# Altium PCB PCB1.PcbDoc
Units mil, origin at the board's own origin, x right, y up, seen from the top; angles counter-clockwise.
Board outline 2755.91 x 2519.69 mil, 4 copper layers (Top Layer, Layer 1, Layer 2, Bottom Layer), stack 23.756 mil thick; 44 components, 30 nets, 121 pads, 26 vias.
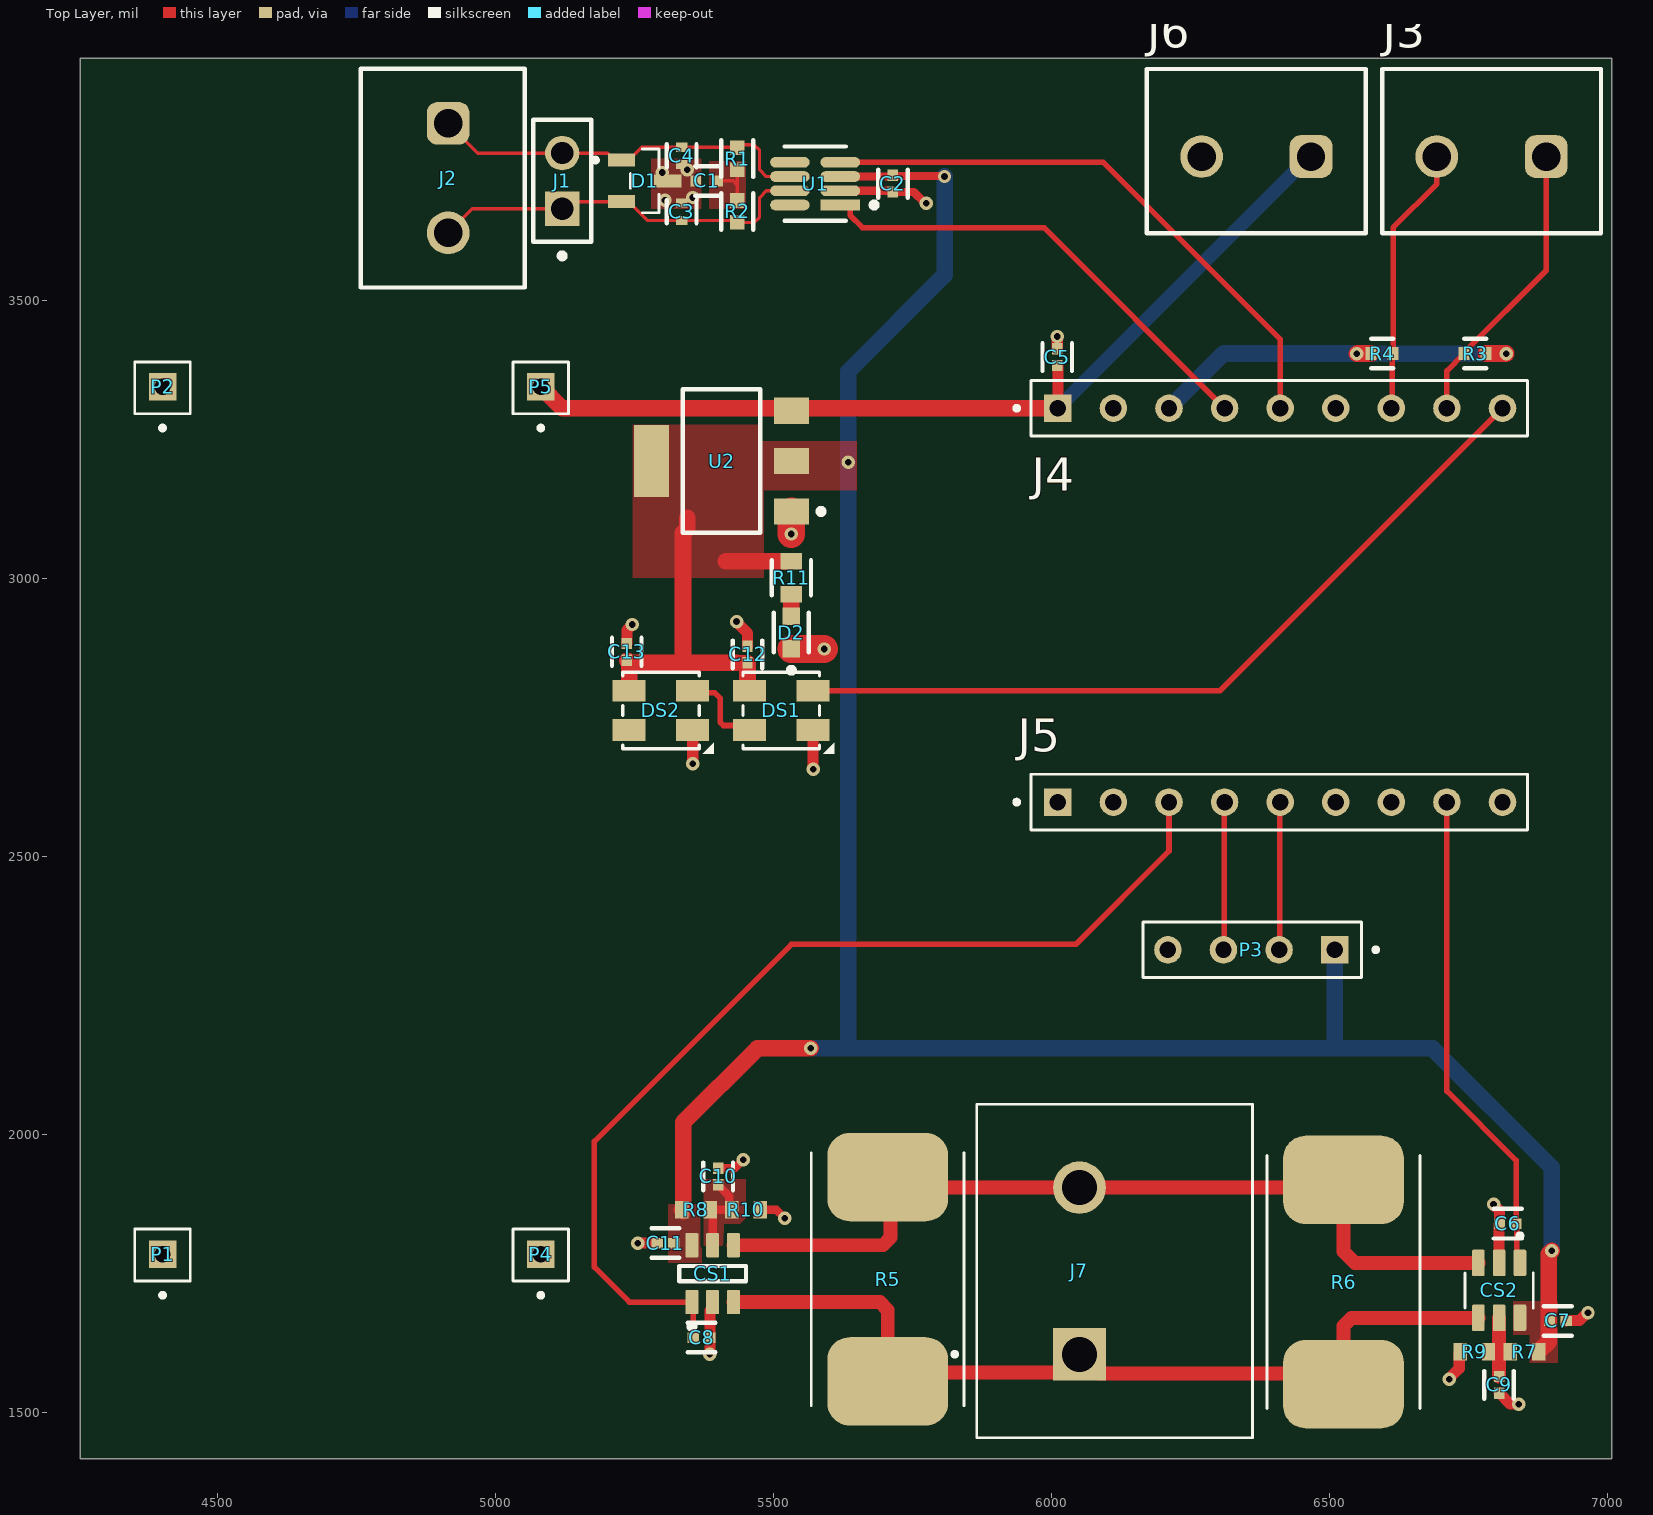
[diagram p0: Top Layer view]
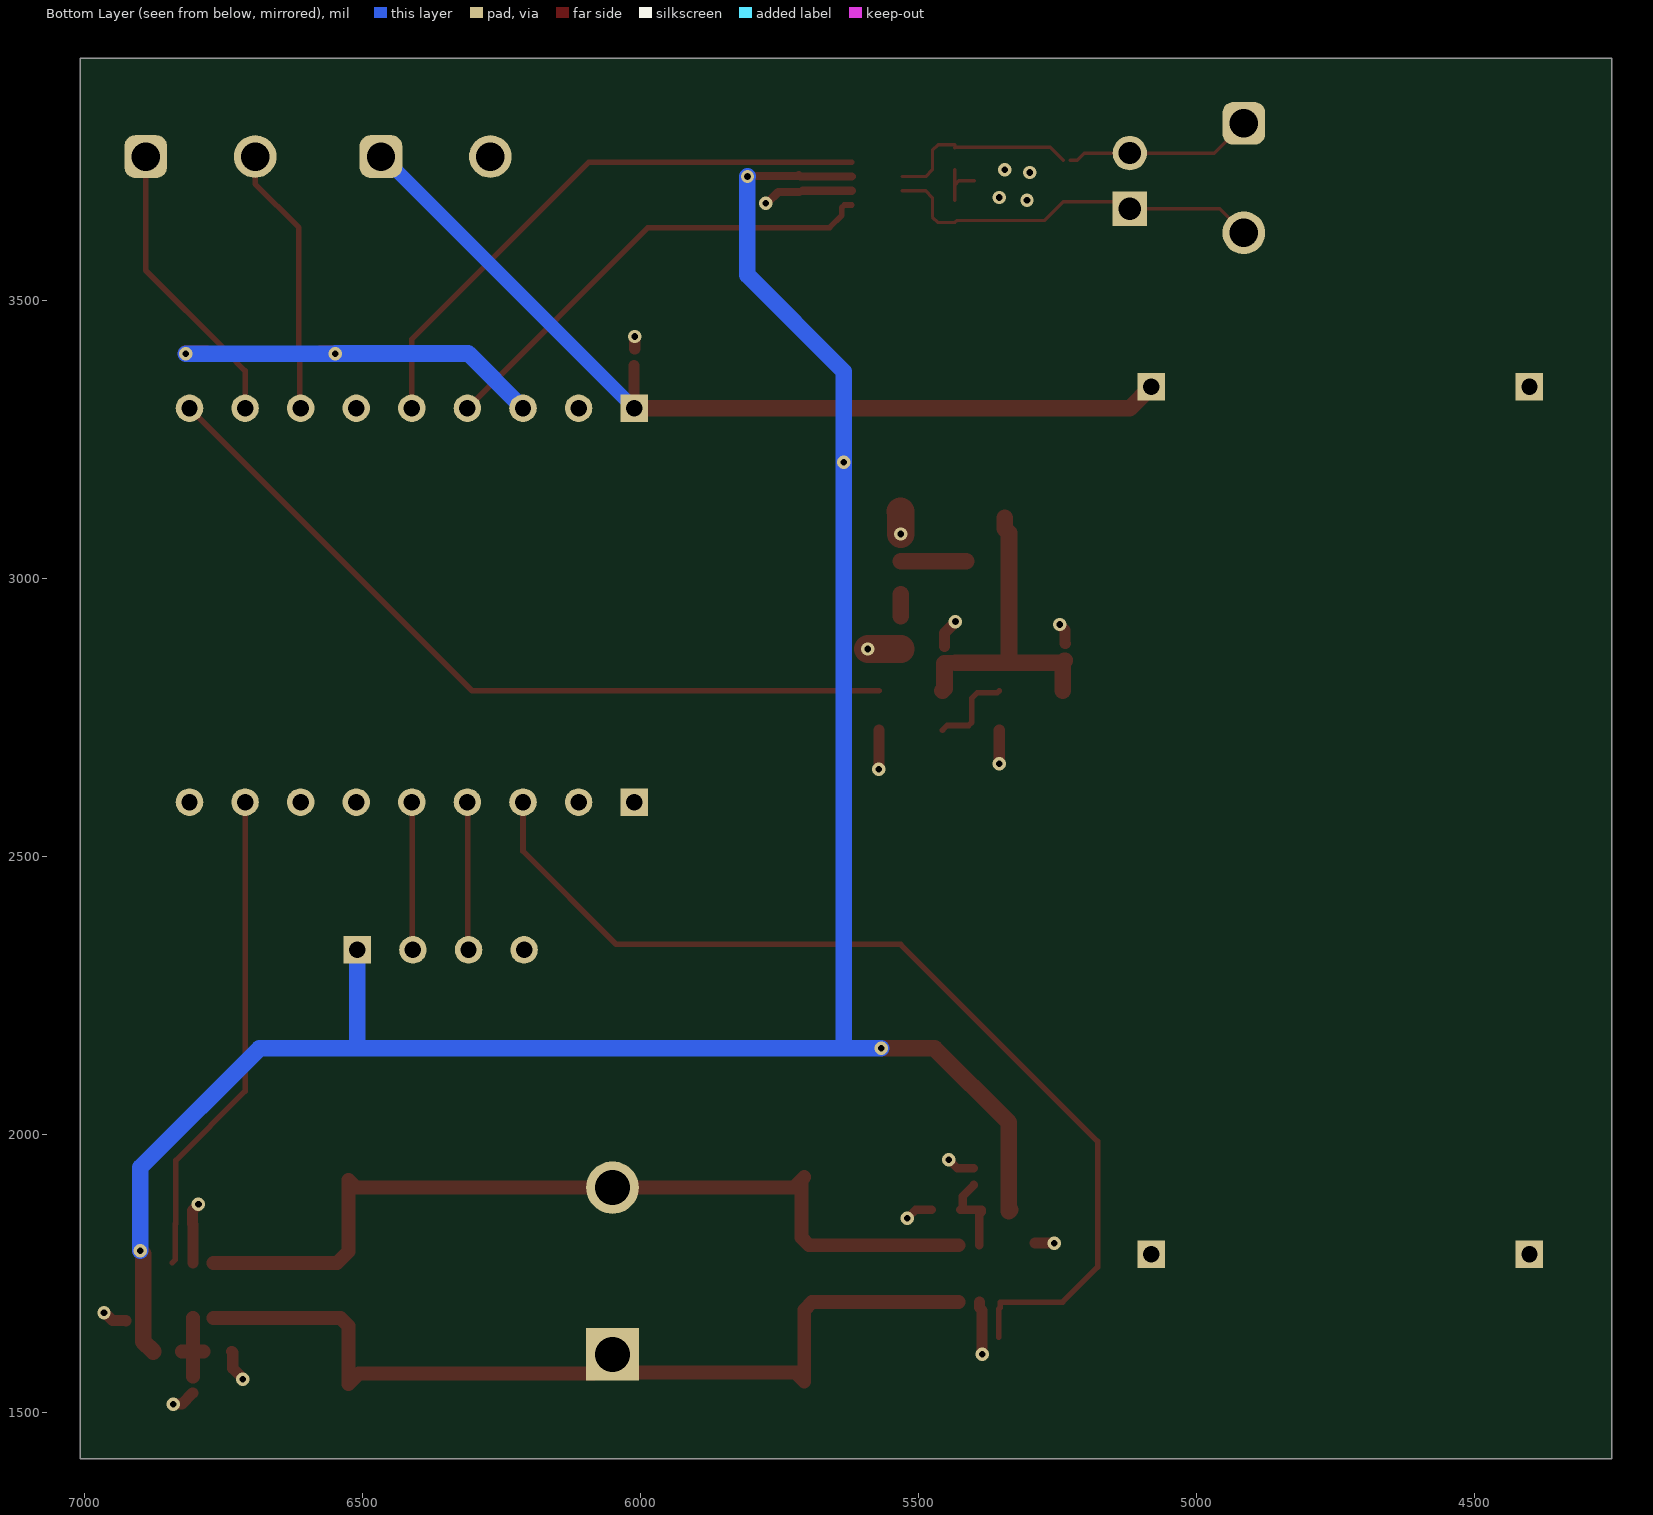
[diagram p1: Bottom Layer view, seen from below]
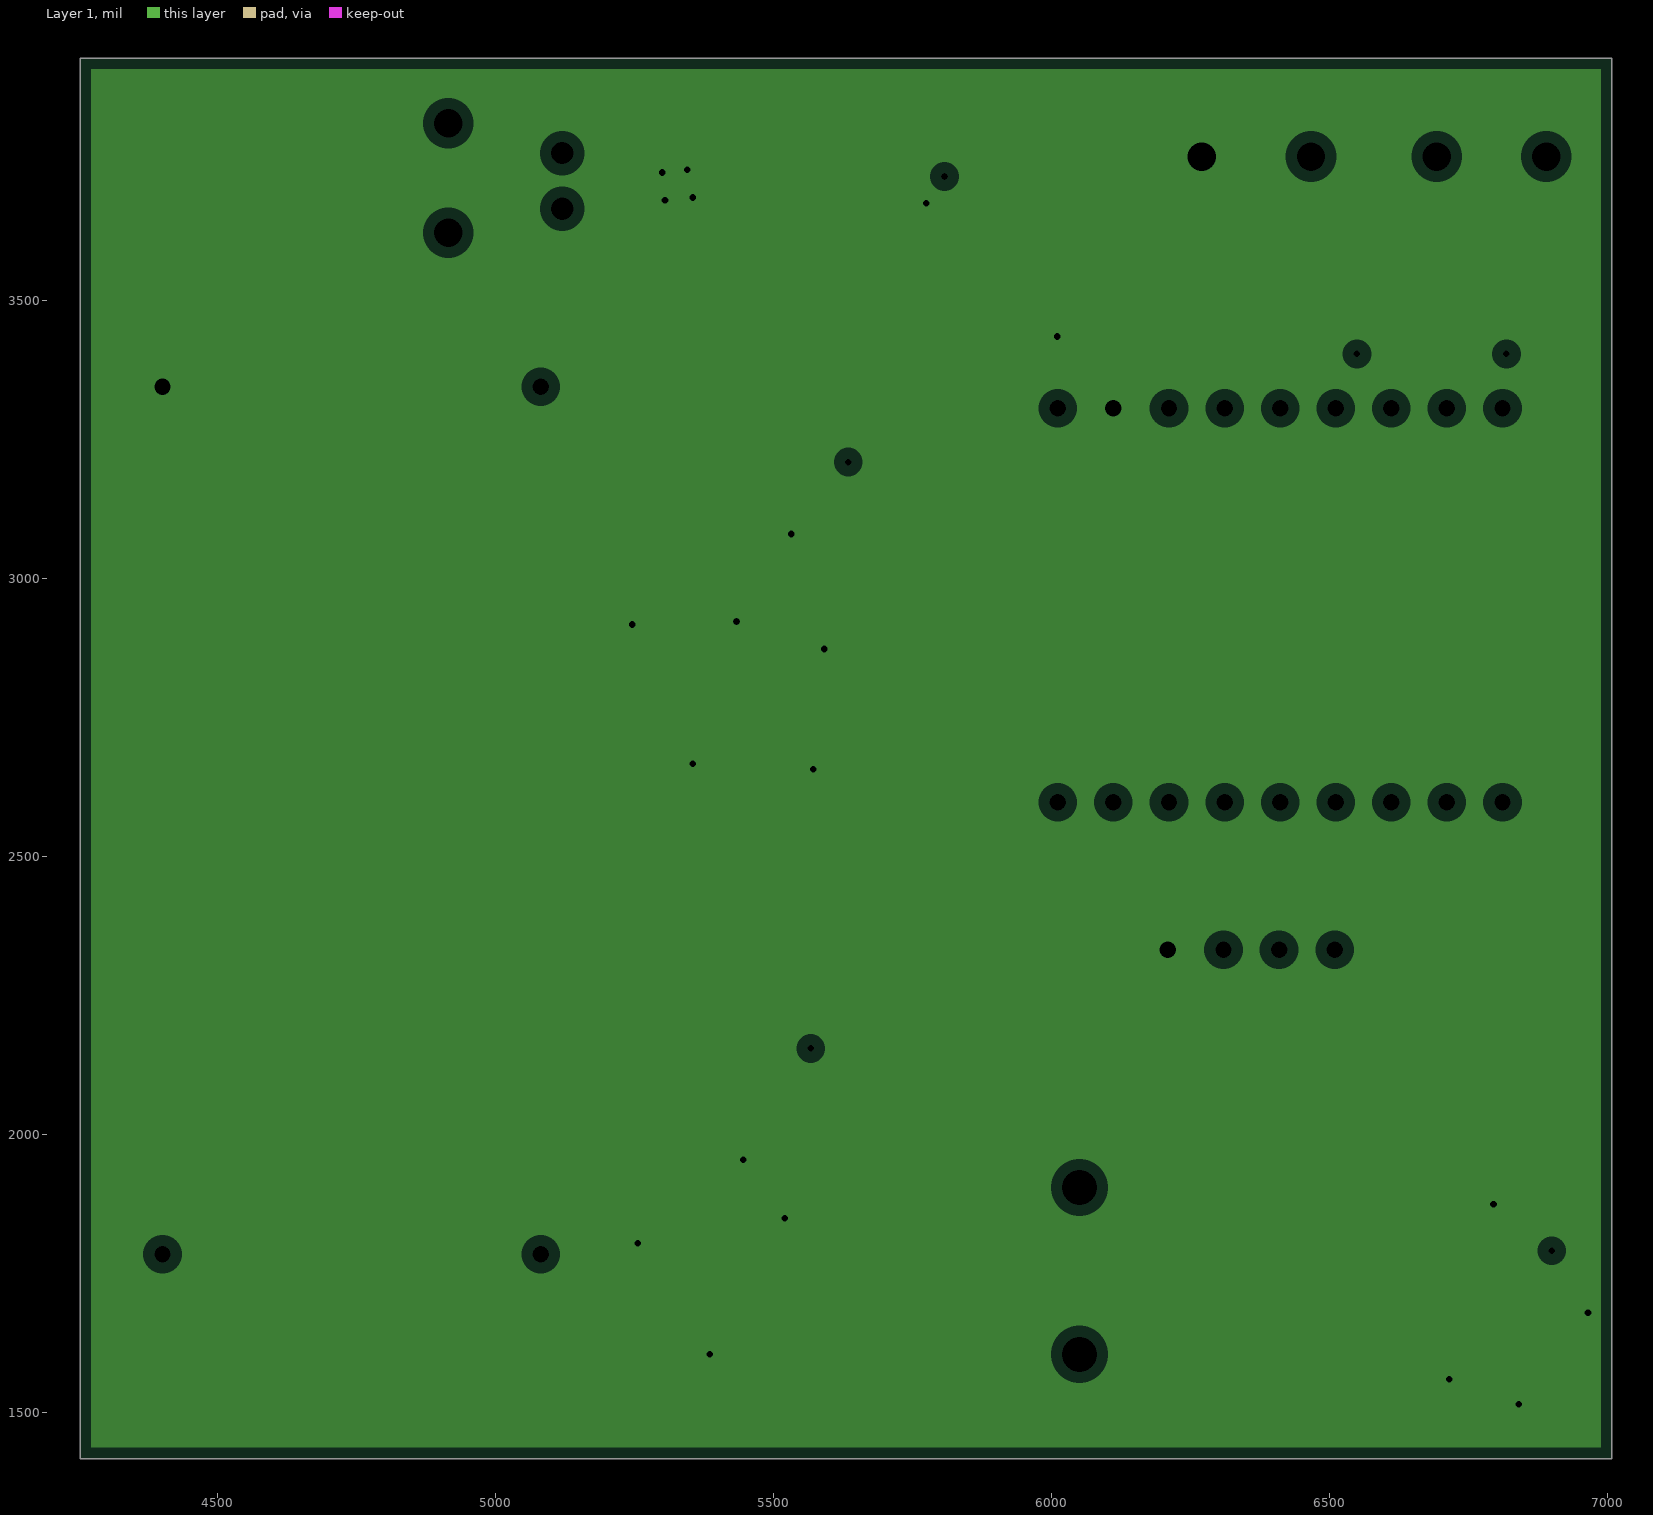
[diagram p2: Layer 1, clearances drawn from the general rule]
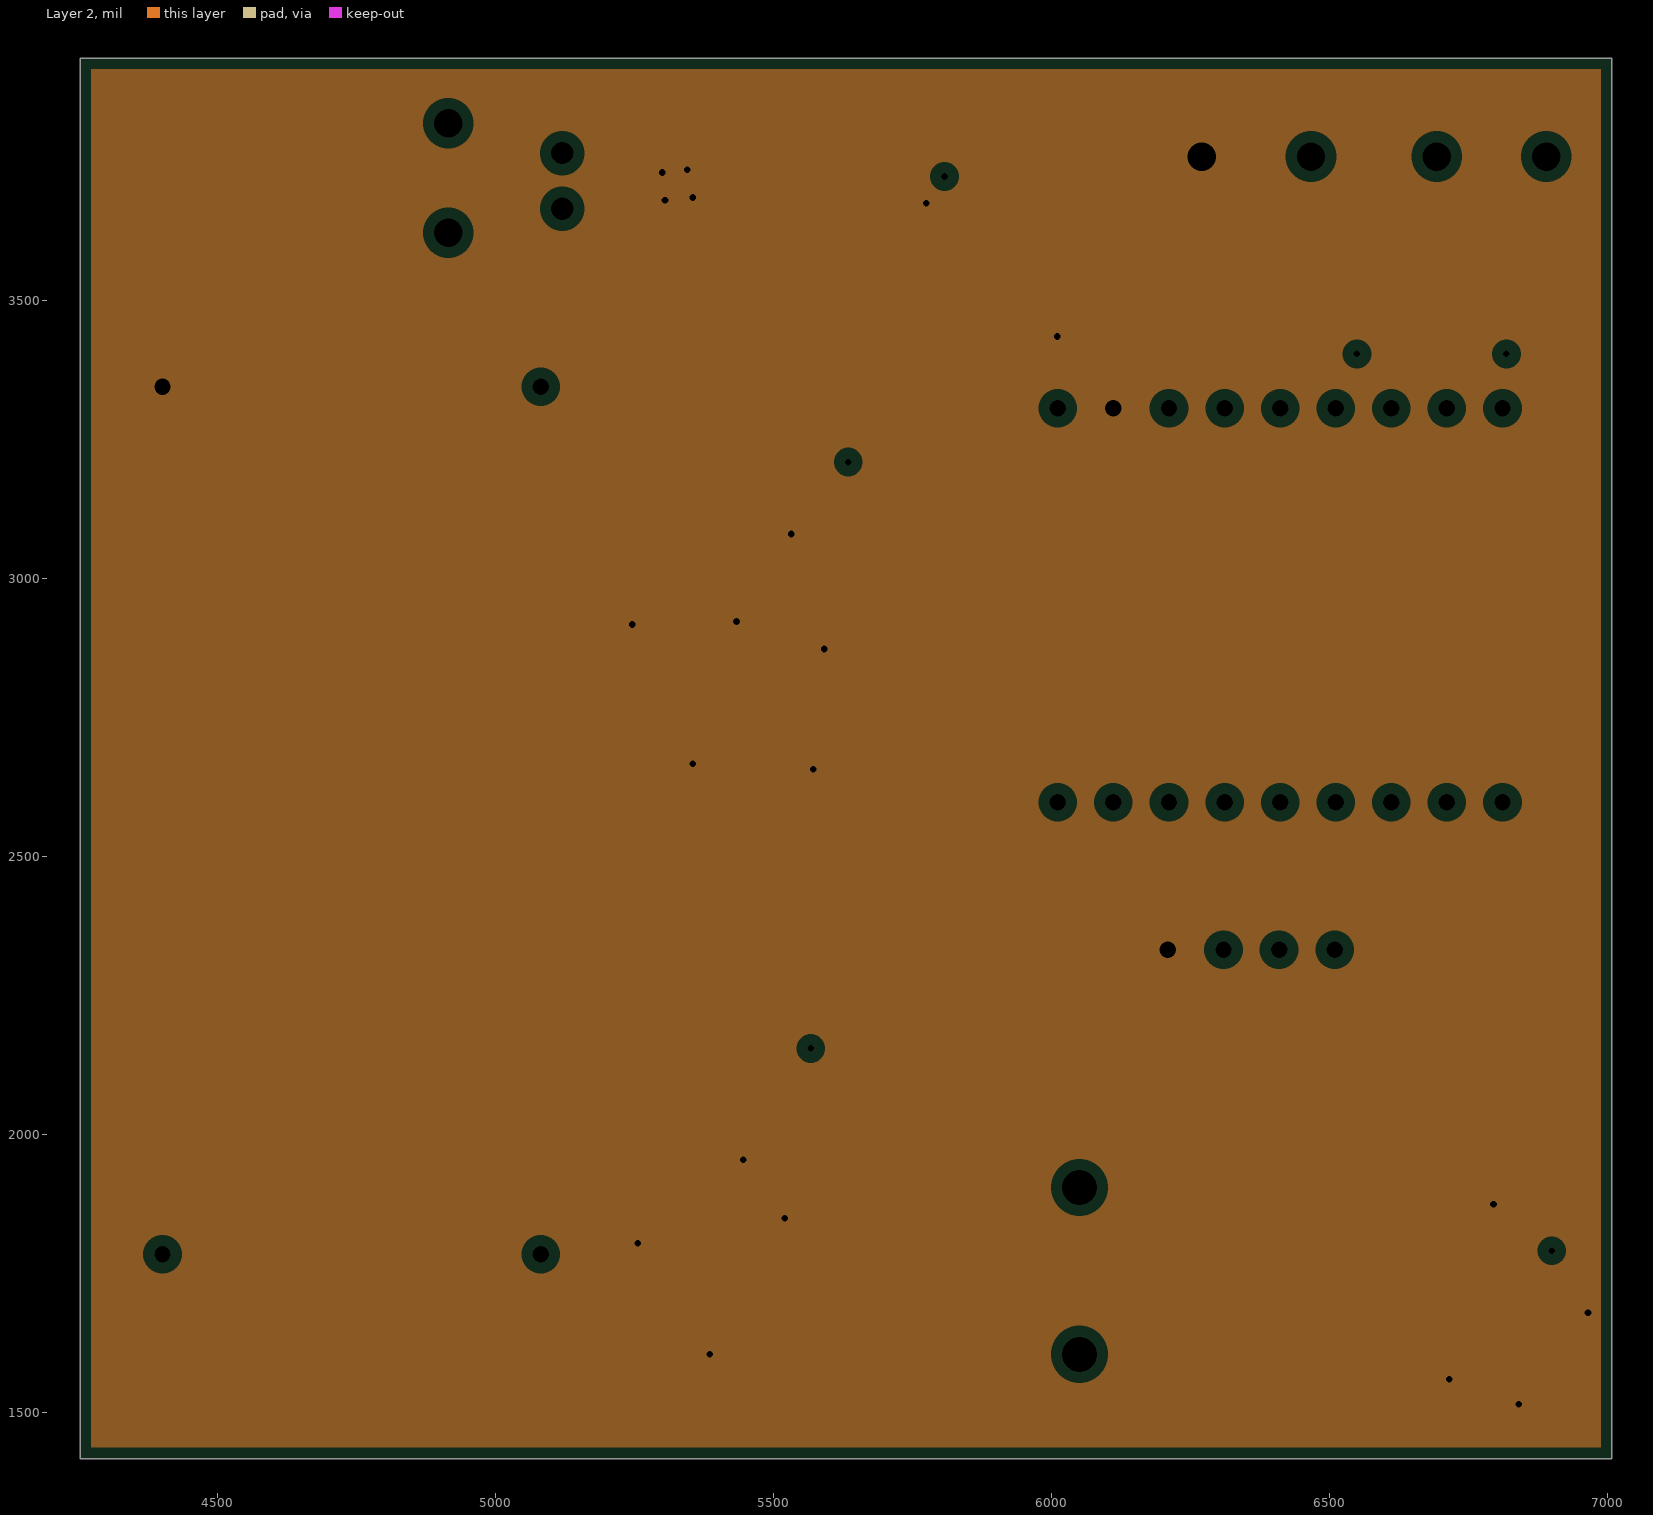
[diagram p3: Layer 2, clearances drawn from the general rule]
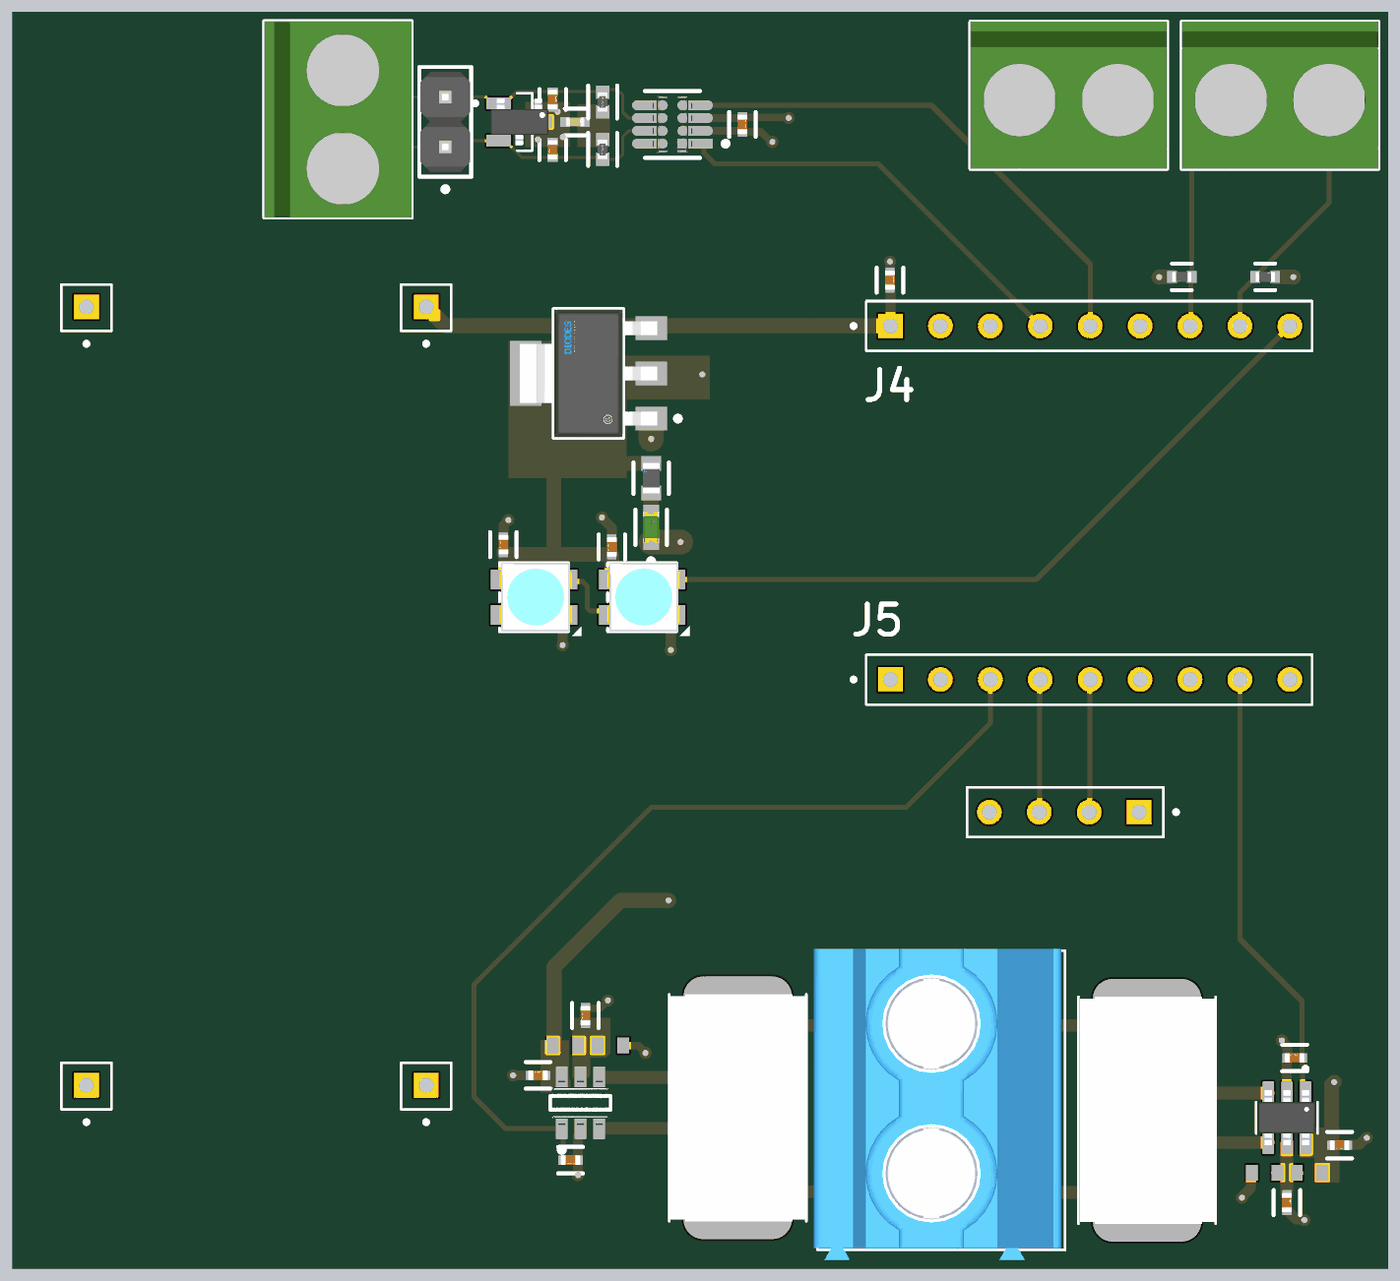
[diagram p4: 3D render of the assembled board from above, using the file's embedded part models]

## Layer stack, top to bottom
Top Solder: solder mask 0.4, Solder Resist, Dk 3.5
Top Layer: signal copper 1.4
Dielectric 2: prepreg 2.8, PP-006, Dk 4.1
Layer 1: plane copper 1.378, net GND
Dielectric 1: dielectric 12.6, FR-4, Dk 4.8
Layer 2: plane copper 1.378, net GND
Dielectric 3: prepreg 2.8, PP-006, Dk 4.1
Bottom Layer: signal copper 1.4
Bottom Solder: solder mask 0.4, Solder Resist, Dk 3.5

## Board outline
4251.97,3937.01 4251.97,1417.32 7007.87,1417.32 7007.87,3937.01

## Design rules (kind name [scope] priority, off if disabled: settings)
Clearance [All] p1: gap=6 ignorepadtopadclearanceinfootprint=FALSE
DiffPairsRouting [All] p1: maxlimit=10 minlimit=10 mostfreqgap=10 toplayer_minwidth=5 toplayer_maxwidth=15 toplayer_prefwidth=15 bottomlayer_minwidth=15 bottomlayer_maxwidth=15 bottomlayer_prefwidth=15 maxuncoupledlength=500
PlaneClearance [All] p1: clearance=20
PlaneConnect [All] p1: pad.planeconnectstyle=Relief pad.reliefexpansion=20 pad.reliefentries=4 pad.reliefconductorwidth=10 pad.reliefairgap=10 via.planeconnectstyle=Direct via.reliefexpansion=20 via.reliefentries=4 via.reliefconductorwidth=10 via.reliefairgap=10
PolygonConnect [All] p1: connectstyle=Direct reliefconductorwidth=10 reliefentries=4 polygonreliefangle="90 Angle" airgapwidth=10
RoutingVias [All] p1: holewidth=12 width=24 viastyle="Through Hole" minholewidth=12 minwidth=24 maxholewidth=12 maxwidth=24
SolderMaskExpansion [All] p1: expansion=4 istentingtop=FALSE
SupplyNets "Schematic Supply Nets_5" [InNet('3V3_2')] p1: voltage=0.000
SupplyNets "Schematic Supply Nets_4" [InNet('GND')] p2: voltage=0.000
SupplyNets "Schematic Supply Nets_3" [InNet('3V3')] p3: voltage=0.000
SupplyNets "Schematic Supply Nets_2" [InNet('+5')] p4: voltage=0.000
SupplyNets "Schematic Supply Nets_1" [InNet('-VIN')] p5: voltage=0.000
SupplyNets "Schematic Supply Nets" [InNet('VIN')] p6: voltage=0.000
Width [All] p1: maxlimit=50 minlimit=6 preferedwidth=10
27 further rules are at their usual default settings.

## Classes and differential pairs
component class Sheet1: C12 C13 D2 DS1 DS2 P1 P2 P4 P5 R11 U2 U3 U4
component class Sheet_1: C5 C6 C7 C8 C9 C10 C11 CS1 CS2 J3 J4 J5 J6 J7 P3 R3 R4 R5 R6 R7 R8 R9 R10
component class CAN: C1 C2 C3 C4 D1 J1 J2 R1 R2 U1

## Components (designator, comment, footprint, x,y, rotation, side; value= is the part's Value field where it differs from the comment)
C1 "CC0402KRX7R6BB472" FP-CC0402-MFG 5379.33,3716.1 r0 top value="4.7 nF"
C2 "CL05B104KP5NNNC" FP-CL17-IPC_C 5714.33,3711.1 r90 top
C3 "CL05C101JB5NNNC" FP-CL05-MFG 5334.33,3660.45 r270 top value=100pF
C4 "CL05C101JB5NNNC" FP-CL05-MFG 5334.33,3761.1 r90 top value=100pF
C5 "CL05A104KA5NNNC" FP-CL278-IPC_C 6010,3399 r90 top
C6 "CL05A104KA5NNNC" FP-CL278-IPC_C 6820.59,1840 r180 top
C7 "CL05A104KA5NNNC" FP-CL278-IPC_C 6910.59,1665 r0 top
C8 "CL05A104KA5NNNC" FP-CL278-IPC_C 5370,1635 r0 top
C9 "CL05A104KA5NNNC" FP-CL278-IPC_C 6805,1550 r90 top
C10 "CL05A104KA5NNNC" FP-CL278-IPC_C 5400,1925 r270 top
C11 "CL05A104KA5NNNC" FP-CL278-IPC_C 5305,1805 r180 top
C12 "CL05A104KA5NNNC" FP-CL278-IPC_C 5452.76,2864.17 r270 top
C13 "CL05A104KA5NNNC" FP-CL278-IPC_C 5235.52,2868.81 r270 top
CS1 "INA181A1IDBVR" FP-DBV0006A-MFG 5390,1750 r90 top
CS2 "INA181A3IDBVR" SOT95P280X145-6N 6805,1720 r270 top
D1 "ESD2CAN24DBZRQ1" SOT95P237X112-3N 5267.8,3716.1 r0 top
D2 "VLMS1300-GS08" FP-6_541-5092_01-4-MFG 5531.5,2903.54 r90 top
DS1 "SK6812MINI-HS" LED 5511.81,2765.75 r0 top
DS2 "SK6812MINI-HS" LED 5295.28,2765.75 r0 top
J1 "M20-9990246" FP-M20-9990246-MFG 5119.33,3716.1 r90 top
J2 "691137710002" 691137710002 4904.33,3721.1 r270 top
J3 "691137710002" 691137710002 6791.34,3769.68 r180 top
J4 "2PH1-09-UA" "2AMPHENOL_76341-322LF - duplicate" 7061.02,3307.09 r180 top locked
J5 "2PH1-09-UA" "2AMPHENOL_76341-322LF - duplicate" 7061.02,2598.43 r180 top locked
J6 "691137710002" 691137710002 6368.11,3769.68 r180 top
J7 "TB005-762-02BE" CUI_TB005-762-02BE 6050,1605 r90 top
P1 "Header-Male-2.54_1x1" PCBCOMPONENT_1 4400.26,1785.24 r270 top
P2 "Header-Male-2.54_1x1" PCBCOMPONENT_1 4400.26,3345.47 r270 top
P3 "Header-Female-2.54_1x4" "4 PIN CONNECTOR MALE" 5609.06,2177.68 r0 top
P4 "Header-Male-2.54_1x1" PCBCOMPONENT_1 5080.83,1785.24 r270 top
P5 "Header-Male-2.54_1x1" PCBCOMPONENT_1 5080.83,3345.47 r270 top
R1 "ERJ-2RKF60R4X" FP-ERJ2RK-IPC_A 5434.33,3756.1 r270 top
R2 "ERJ-2RKF60R4X" FP-ERJ2RK-IPC_A 5434.33,3661.1 r90 top
R3 "RC0402JR-074K7L" FP-RC0402-0_4-MFG 6761.81,3405.51 r0 top
R4 "RC0402JR-074K7L" FP-RC0402-0_4-MFG 6594.49,3405.51 r180 top
R5 "WSR32L000FEA" RESM11569X253N 5705,1740 r90 top value=2mR
R6 "WSR32L000FEA" RESM11569X253N 6525,1735 r90 top value=2mR
R7 "RC0603FR-1010KL" RESC1608X55X25LL10T15 6850.59,1610 r0 top
R8 "RC0603FR-1010KL" RESC1608X55X25LL10T15 5360,1865 r180 top
R9 "RC0603FR-1010KL" RESC1608X55X25LL10T15 6760.59,1610 r0 top
R10 "RC0603FR-1010KL" RESC1608X55X25LL10T15 5450,1865 r180 top
R11 "CRCW06031K00FKEA" FP-CRCW0603-e3-MFG 5531.5,3001.97 r90 top value=1kR
U1 "TCAN332GDCNR" FP-DCN0008A-IPC_A 5574.33,3711.1 r180 top
U2 "AZ1117CH-3.3TRG1" FP-SOT223-MFG 5406,3212 r180 top

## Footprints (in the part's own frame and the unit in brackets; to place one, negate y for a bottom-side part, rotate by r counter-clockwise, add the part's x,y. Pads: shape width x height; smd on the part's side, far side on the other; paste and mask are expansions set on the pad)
"2AMPHENOL_76341-322LF - duplicate" [mm]
  rect 1.258x1.258 / inner round 1.258 / far side rect 1.258x1.258 hole 0.75: 1(26.67,0)
  round 1.258 hole 0.75: 2(24.13,0) 3(21.59,0) 4(19.05,0) 5(16.51,0) 6(13.97,0) 7(11.43,0) 8(8.89,0) 9(6.35,0)
  silkscreen extent 5.21,-1.27 28.65,1.27
"4 PIN CONNECTOR MALE" [mil]
  rect 49.53x49.53 / inner round 49.53 / far side rect 49.53x49.53 hole 29.53: 1(900,155)
  round 49.53 hole 29.53: 2(800,155) 3(700,155) 4(600,155)
  silkscreen extent 555,105 978,205
691137710002 [mm] "Horizontal Cable Entry with Pressure Clamp, pitch 5mm, 02p"
  rrect50% 1.95x1.95 hole 1.3: 1(-2.5,0.25)
  round 1.95 hole 1.3: 2(2.5,0.25)
  silkscreen extent -5,-3.75 5,3.75, body extent -5,-3.75 5,3.75, height 11.6
CUI_TB005-762-02BE [mm]
  rect 2.4x2.4 / inner round 2.4 / far side rect 2.4x2.4 hole 1.6: 1(0,0)
  round 2.4 hole 1.6: 2(7.62,0)
  silkscreen extent -3.81,-7.9 11.43,5.8, body extent -4.32,-7.7 11.52,4.9, height 21.7
FP-6_541-5092_01-4-MFG [mm]
  rect 0.8x0.8 smd paste+0 mask+0: 1(-0.75,0) 2(0.75,0)
  silkscreen extent -1.85,-0.8 0.9,0.8, body extent -1.25,-0.6 1.25,0.6, height 0.25
FP-CC0402-MFG [mm]
  rect 0.5x0.5 smd paste+0 mask+0: 1(-0.5,0) 2(0.5,0)
  silkscreen extent -0.53,-0.68 0.53,0.67, body extent -0.87,-0.48 0.87,0.48, height 0.25
FP-CL05-MFG [mm]
  rect 0.42x0.525 smd paste+0 mask+0: 1(-0.397,0) 2(0.397,0)
  silkscreen extent -0.53,-0.67 0.53,0.67, body extent -0.71,-0.38 0.71,0.38, height 0.25
FP-CL17-IPC_C [mil]
  rect 20.29x18.6 smd paste+0 mask+0: 1(-14.9,0) 2(14.9,0)
  silkscreen extent -25,-27 25,27, body extent -29,-15 29,15, height 10
FP-CL278-IPC_C [mil]
  rect 20.29x18.6 smd paste+0 mask+0: 1(-14.9,0) 2(14.9,0)
  silkscreen extent -25,-27 25,27, body extent -29,-15 29,15, height 10
FP-CRCW0603-e3-MFG [mm]
  rect 0.75x1 smd paste+0 mask+0: 1(-0.75,0) 2(0.75,0)
  silkscreen extent -0.8,-0.9 0.8,0.9, body extent -1.22,-0.6 1.22,0.6, height 0.25
FP-DBV0006A-MFG [mm]
  rrect17% 1.1x0.6 smd paste+0 mask+0: 1(-1.3,0.95) 2(-1.3,0) 3(-1.3,-0.95) 4(1.3,-0.95) 5(1.3,0) 6(1.3,0.95)
  silkscreen extent -2.52,-1.53 0.35,1.53, body extent -1.95,-1.78 1.95,1.78, height 0.25
FP-DCN0008A-IPC_A [mm]
  rect 1.805x0.495 smd paste+0 mask+0: 1(-1.15,0.975)
  rrect100% 1.805x0.495 smd paste+0 mask+0: 2(-1.15,0.325) 3(-1.15,-0.325) 4(-1.15,-0.975) 5(1.15,-0.975) 6(1.15,-0.325) 7(1.15,0.325) 8(1.15,0.975)
  silkscreen extent -2.83,-1.7 1.4,1.7, body extent -2.55,-1.95 2.55,1.95, height 0.25
FP-ERJ2RK-IPC_A [mil]
  rect 26.31x26.48 smd paste+0 mask+0: 1(-19.77,0) 2(19.77,0)
  silkscreen extent -33,-29 33,29, body extent -41,-21 41,21, height 10
FP-M20-9990246-MFG [mm]
  rect 1.57x1.57 hole 1.02 paste-2539.97 mask+0: 1(-1.27,0)
  round 1.57 hole 1.02 paste-2539.97 mask+0: 2(1.27,0)
  silkscreen extent -3.55,-1.32 2.79,1.32, body extent -2.89,-1.42 2.89,1.42, height 0.25
FP-RC0402-0_4-MFG [mm]
  rect 0.5x0.6 smd paste+0 mask+0: 1(-0.5,0) 2(0.5,0)
  silkscreen extent -0.5,-0.67 0.5,0.67, body extent -0.85,-0.4 0.85,0.4, height 0.25
FP-SOT223-MFG [mm]
  rect 1.6x1.2 smd paste+0 mask+0: 1(-3.2,2.3) 2(-3.2,0) 3(-3.2,-2.3)
  rect 1.6x3.3 smd paste+0 mask+0: 4(3.2,0)
  silkscreen extent -4.68,-3.27 1.78,3.27, body extent -4.1,-3.37 4.1,3.37, height 0.25
LED [mm]
  rect 1.5x1 smd: 1(1.491,-0.96) 2(1.491,0.841) 3(-1.409,0.841) 4(-1.409,-0.96)
  silkscreen extent -1.71,-2.03 2.46,1.69, body extent -1.72,-1.8 1.98,1.7, height 1
PCBCOMPONENT_1 [mm]
  rect 1.258x1.258 / inner round 1.258 / far side rect 1.258x1.258 hole 0.75: 1(0,0)
  silkscreen extent -1.14,-1.27 1.98,1.27
RESC1608X55X25LL10T15 [mm] "Chip Resistor, 2-Leads, Body 1.60x0.80mm, IPC High Density"
  rect 0.6x0.8 smd: 1(-0.65,0) 2(0.65,0)
  body extent -0.85,-0.45 0.85,0.45, height 0.55
RESM11569X253N [mm]
  rrect50% 4.04x5.51 smd: 1(-4.665,0) 2(4.665,0)
  silkscreen extent -5.78,-3.49 5.78,3.49, body extent -5.78,-3.56 5.78,3.42, height 2.42
SOT95P237X112-3N [mm]
  rect 1.24x0.59 smd: 1(-1.055,0.95) 2(-1.055,-0.95) 3(1.055,0)
  silkscreen extent -2.35,-1.46 0.65,1.46, body extent -1.18,-1.46 1.18,1.46, height 1.12
SOT95P280X145-6N [mm]
  rrect25% 1.21x0.58 smd: 1(-1.255,0.95) 2(-1.255,0) 3(-1.255,-0.95) 4(1.255,-0.95) 5(1.255,0) 6(1.255,0.95)
  silkscreen extent -2.6,-1.56 0.8,1.56, body extent -1.4,-1.45 1.4,1.45, height 1.45

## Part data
C1: library part CMP-03422-001343-1, "CC0402 4.7 nF X7R 10.00% 10 V", Capacitance="4.7 nF", Manufacturer=YAGEO, Package=CC0402, Temperature="-55°C to +125°C", Temperature Characteristic=X7R, Temperature Coefficient=30ppm/°C, Temperature Range High=+125°C, Temperature Range Low=-55°C, Tolerance=0.1, Voltage Rating="10 V"
C2: library part CMP-13271-001069-1, "Cap Ceramic 100nF 10V X7R ±10% SMD 0402 +125°C Paper T/R", Capacitance=100nF, Case Code (Imperial)=0402, Case Code (Metric)=1005, Dielectric=X7R, Max Operating Temperature=125°C, Min Operating Temperature=-55°C, Package Quantity=1, Tolerance=10%, Voltage Rating=10V
C3 C4: library part CMP-13271-000010-1, "CAP CER 100PF 50V C0G/NP0 0402", Capacitance=100pF, Manufacturer=Samsung, Package=CL05, Temperature="-55°C to +125°C", Temperature Characteristic=C0G, Temperature Coefficient=30ppm/°C, Temperature Range High=+125°C, Temperature Range Low=-55°C, Tolerance=5%, Voltage Rating=50V
C5 C6 C7 C8 C9 C10 C11 C12 C13: library part CMP-13271-000728-1, "Cap Ceramic 100nF 25V X5R ±10% SMD 0402 +85°C Paper T/R", Capacitance=100nF, Case Code (Imperial)=0402, Case Code (Metric)=1005, Dielectric=X5R, Max Operating Temperature=85°C, Min Operating Temperature=-55°C, Package Quantity=1, Tolerance=10%, Voltage=25V
CS1: library part CMP-04895-000055-1, "IC CURR SENSE 1 CIRCUIT SOT23-6", Ambient Temperature Range High=+125°C, Ambient Temperature Range Low=-40°C, Input Bias Current=75uA, Input Offset Voltage=0.1mV, Manufacturer="Texas Instruments", Max Junction Temp=+150°C, Max Supply Voltage=5.5V, Min Supply Voltage=2.7V, Nominal Supply Current=195uA, Output Current Per Channel=8mA, Package=DBV0006A, Temperature="-40°C to +125°C", Voltage Gain=0.02V/mV
CS2: "Operational Amplifier, 1 Func, 500uV Offset-Max, PDSO6", Average Bias Current-Max (IIB)=75uA, Case/Package=SOP, Input Offset Voltage-Max=500uV, Manufacturer="Texas Instruments", Max Operating Temperature=125°C, Min Operating Temperature=-40°C, Nominal Supply Voltage=5V, Package Body Material=Plastic, Package Shape=Rectangular, Package Style="SMALL OUTLINEMeter", Peak Reflow Temperature (Cel)=260°C, Supplier Part Number=296-47658-1-ND, Supply Voltage Limit-Max=5.5V, Temperature Grade=AUTOMOTIVE
D1: "Automotive, dual, 3-pF, ±24-V, ±30-kV ESD protection diode for CAN and in-vehicle networks 3-SOT-23 -55 to 150", Manufacturer="Texas Instruments", Supplier Part Number=296-ESD2CAN24DBZRQ1CT-ND
D2: library part CMP-02520-000012-1, "LED RED 0603 SMD", Ambient Temperature Range High=+85°C, Ambient Temperature Range Low=-35°C, Colour=Red, Forward Current=20mA, Forward Voltage=2V, Manufacturer=Vishay, Package=6.541-5092.01-4, Power Dissipation=75mW, Reverse Voltage=5V, Temperature="-35°C to +85°C"
J1: library part CMP-15831-000009-1, "CONN HEADER VERT 2POS 2.54MM", Current Rating=3A, Manufacturer=Harwin, Temperature="-40°C to +105°C", Temperature Range High=+105°C, Temperature Range Low=-40°C
J2 J3 J6: library part CMP-1502-03324-2, Current Rating=16A, Max Operating Temperature=120°C, Min Operating Temperature=-30°C, Voltage Rating=300V
J4 J5: "Conn Unshrouded Header HDR 9 POS 2mm Solder ST Thru-Hole", Contact Resistance=20mΩ, Current Rating=1A, Insulation Resistance=5GΩ, Manufacturer="Adam Tech", Max Operating Temperature=105°C, Min Operating Temperature=-55°C, Supplier Part Number=2057-2PH1-09-UA-ND
J7: "Barrier Strip Terminal Block", Manufacturer="Same Sky", Supplier Part Number=102-6189-ND
P1 P2 P4 P5: JLCPCB Part Class="Extended Part", Manufacturer=BOOMELE(博穆精密), Manufacturer Part=2.54-1*1P针
P3: Manufacturer=ReliaPro
R1 R2: library part CMP-2002-01013-2, "RES SMD 60.4 OHM 1% 1/10W 0402", Case Code (Imperial)=0402, Case Code (Metric)=1005, Max Operating Temperature=155°C, Max Power Dissipation=100mW, Min Operating Temperature=-55°C, Package Quantity=1, Resistance=60.4R, Resistance Tolerance=1%, Resistor Type="Thick Film", Temperature Coefficient=100ppm/°C, Voltage Rating=50V
R3 R4: library part CMP-2002-08011-2, Case Code (Imperial)=0402, Max Operating Temperature=155°C, Max Power Dissipation=63mW, Min Operating Temperature=-55°C, Resistance=4.7kΩ, Temperature Coefficient=100ppm/°C, Tolerance=5%, Voltage Rating=50V
R5 R6: "Fixed Resistor, Metal Strip, 3W, 0.002ohm, 0.077V, 1% +/-Tol, 600ppm/Cel, Surface Mount, 4527", Case/Package=4527, Manufacturer="Vishay Dale", Max Operating Temperature=275°C, Min Operating Temperature=-65°C, Package Height=2.41mm, Package Length=11.56mm, Package Shape=Rectangular, Package Width=6.98mm, Power=3W, Rated Temperature=70°C, Resistor Type="FIXED RESISTOR", Supplier Part Number=WSRB-.002CT-ND, Temperature Coefficient (ppm/Cel)=-600,600, Tolerance=1%
R7 R8 R9 R10: library part CMP-2000-06948-1, "Chip Resistor, 10 kOhm, +/- 1%, 0.1 W, -55 to 155 degC, 0603 (1608 Metric), RoHS, Tape and Reel", Case Style=Molded, Manufacturer=Yageo, Operating Temp Range=-55Cto155C, Package / Case=0603, Package Description="2-Pin Surface Mount Device, Body 1.6 x 0.8 mm", Power Rating(s)=1/10W, Resistance=10kohm, Temperature Coefficient=±100, Tolerance (+ or -)=1%
R11: library part CMP-1666-00003-5, "RES Thick Film, 1kΩ, 1%, 0.1W, 100ppm/°C, 0603", Case Code (Imperial)=0603, Case Code (Metric)=1608, Max Operating Temperature=155°C, Max Power Dissipation=100mW, Min Operating Temperature=-55°C, Package Quantity=10, Resistance=1kR, Temperature Coefficient=100ppm/°C, Tolerance=1%, Voltage Rating=75V
U1: library part CMP-04872-000119-1, "IC TRANSCEIVER 1/1 SOT23-8", Case/Package=SOT-23-8, Max Operating Temperature=125°C, Min Operating Temperature=-40°C
U2: library part CMP-12756-000028-1, "IC REG LINEAR 3.3V 800MA SOT223", Case/Package=SOT-223, Dropout Voltage=1.2V, Max Input Voltage=15V, Max Operating Temperature=125°C, Max Output Current=1.35A, Min Current Limit=1A, Min Operating Temperature=-20°C, Output Current=800mA, Output Voltage=3.3V, Package Quantity=4000, Power Supply Rejection Ratio (PSRR)=70dB, Quiescent Current=6mA, Reference Voltage=1.262V

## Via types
v1: diameter 24, hole 12, Top Layer to Bottom Layer, tented both sides, 26 vias

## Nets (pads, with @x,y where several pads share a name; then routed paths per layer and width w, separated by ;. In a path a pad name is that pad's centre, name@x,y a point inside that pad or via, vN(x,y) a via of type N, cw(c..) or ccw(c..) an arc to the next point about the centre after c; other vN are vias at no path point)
3V3: C2.2 C7.1 C11.1 C12.2 C13.2 CS1.6 CS2.6 DS1.3 DS2.3 P3.1 R7.2 R8.2 R11.2 U1.3 U2.2 U2.4 | length 4927.4
  Top Layer w15: U1.3 5712.53,3723.9 5714.64,3726.01 5715.64,3725 5806,3725 v1(5807,3724)
  Top Layer w27.33: C13.2 C13.2@5236.86,2852.57 ; 5433.42,2849.27 C12.2
  Top Layer w30: DS2.3 5239.8,2849.62 5236.86,2852.57 5240.16,2849.27 5336.79,2849.27 ; R8.2 5337,1862.41 5337,2022 5470.51,2155.51 v1(5566.46,2155.51) ; 5344.49,3110.24 5344.49,3090.55 5336.79,3082.85 5336.79,2849.27 ; 5413.39,3031.5 R11.2 ; 5433.42,2849.27 5336.79,2849.27 ; C12.2@5452.76,2847.93 5452.76,2802.42 DS1.3 ; R7.2 6894.35,1628.17 6894.35,1786.08 v1(6899.61,1791.34)
  Bottom Layer w30: v1(5566.46,2155.51) 5636,2155.51 ; v1(5807,3724) 5807.33,3723.67 5807.33,3546.55 5634,3373.22 v1(5634,3210) 5634,2157.51 5636,2155.51 ; P3.1 6509.06,2160.46 6514,2155.51 ; v1(6899.61,1791.34) 6899.61,1941.39 6685.49,2155.51 6514,2155.51 ; 5636,2155.51 6514,2155.51
3V3_2: J4.3 R3.2 R4.2 | length 710.7
  Top Layer w30: v1(6549,3405) 6549.51,3405.51 R4.2 ; R3.2 6817.49,3405.51 v1(6818,3405)
  Bottom Layer w30: J4.3 6309.45,3405.51 6548.49,3405.51 v1(6549,3405) v1(6818,3405)
+5: C5.1 J4.1 J6.1 P5.1 U2.3 | length 1666.2
  Top Layer w20: J4.1 C5.1@6011.02,3384.1
  Top Layer w30: P5.1 5119.21,3307.09 J4.1
  Bottom Layer w25: J4.1 6463.78,3759.84 J6.1
-VIN: P1.1
CAN_N: C4.2 D1.1 J1.2 J2.1 R1.1 U1.6 | length 684
  Top Layer w6: J2.1 4967.6,3766.1 5201.34,3766.1 5204.85,3762.59 5204.85,3762.12 5213.46,3753.5 D1.1 ; D1.1@5239.06,3753.5 5262.3,3776.75 C4.2 5433.45,3776.75 R1.1 ; R1.1@5434.33,3780.87 5434.56,3781.1 5464.33,3781.1 5474.33,3771.1 5474.33,3736.1 5486.54,3723.9 U1.6
CAN_P: C3.2 D1.2 J1.1 J2.2 R2.1 U1.7 | length 697.8
  Top Layer w6: J2.2 4957.6,3666.1 J1.1 5131.93,3678.7 D1.2 5239.06,3678.7 5272.95,3644.8 C3.2 5430.86,3644.8 R2.1 5434.56,3641.1 5464.33,3641.1 5474.33,3651.1 5474.33,3686.1 5486.54,3698.31 U1.7
GND: C1.1 C2.1 C3.1 C4.1 C5.2 C6.2 C7.2 C8.2 C9.1 C10.1 C11.2 C12.1 C13.1 CS1.2 CS2.2 D1.3 D2.1 DS1.1 DS2.1 J4.2 J6.2 P2.1 P3.4 R9.1 R10.1 U1.2 U2.1 | length 990.4
  Top Layer w15: C10.1 5429.9,1939.9 v1(5445,1955) ; R10.1 5505,1865 v1(5520,1850) ; U1.2 C2.1@5707.78,3698.31 ; C2.1 5751.8,3696.2 5771.9,3676.1 v1(5774.33,3676.1)
  Top Layer w20: C13.1 5236.08,2883.71 5236.22,2883.86 5236.22,2907.8 5245.36,2916.94 v1(5245.36,2918.02) ; v1(5255,1805) C11.2 ; DS2.1 5354.16,2727.8 5354.16,2667.5 v1(5354.33,2667.32) ; C8.2 5384.95,1634.95 v1(5385,1605) v1(5385,1605) ; C8.2@5384.9,1635.7 5384.9,1683.88 5390,1688.98 CS1.2 ; v1(5433.07,2923.23) 5433.07,2922.15 5452.76,2902.46 5452.76,2893.93 ; DS1.1 5570.69,2727.8 5570.69,2657.65 v1(5570.87,2657.48) ; C5.2 v1(6010,3436) ; v1(6715,1560) 6715,1561.08 6733.19,1579.27 6733.19,1608.19 R9.1 ; v1(6795,1875) 6795,1873.92 6805.54,1863.38 C6.2@6805.54,1840.7 ; C9.1 6805.55,1535.1 6824.89,1515.77 6839.23,1515.77 v1(6840,1515) ; CS2.2 6805,1838.76 6805.69,1839.45 C6.2 ; C7.2 6925.49,1665.55 6925.64,1665.7 6949.62,1665.7 6963.92,1680 v1(6965,1680)
  Top Layer w20.29: C12.1 5452.76,2893.93
  Top Layer w50: D2.1 v1(5590.55,2874.02) ; v1(5531.5,3080.71) 5531.5,3120.96 U2.1
  other v1: 5304.33,3681.1 5354.33,3686.1 5299.33,3731.1 5344.33,3736.1
GPIO1: J4.4 U1.1 | length 851.1
  Top Layer w10: U1.1 5632.76,3672.72 5637.51,3667.97 5637.51,3653.83 5659.45,3631.89 5986.22,3631.89 J4.4
GPIO2: J4.5 U1.4 | length 1047.5
  Top Layer w10: U1.4 6093.03,3749.49 6411.02,3431.5 J4.5
GPIO3: J4.6
GPIO4: J3.2 J4.7 R4.1 | length 506.4
  Top Layer w10: J4.7 6612.6,3308.66 6612.6,3403.94 R4.1 6614.17,3631.89 6692.91,3710.63 J3.2@6692.91,3779.53
GPIO5: J3.1 J4.8 R3.1 | length 544.5
  Top Layer w10: J4.8 6711.02,3374.41 R3.1 ; R3.1@6742.13,3407.48 6889.76,3555.12 J3.1@6889.76,3779.53
GPIO6: DS1.2 J4.9 | length 1451
  Top Layer w10: DS1.2 6302.78,2798.84 J4.9
GPIO7: J5.9
GPIO8: C6.1 CS2.1 J5.8 | length 883.1
  Top Layer w10: J5.8 6711.02,2078.35 6835.49,1953.88 C6.1 ; C6.1@6836.34,1840 6836.34,1775.47 CS2.1
GPIO9: J5.7
GPIO10: J5.6
GPIO11: J5.5 P3.2 | length 266.6
  Top Layer w10: P3.2 6410.04,2333.66 6410.04,2597.44 J5.5
GPIO12: J5.4 P3.3 | length 266.6
  Top Layer w10: P3.3 6310.04,2333.66 6310.04,2597.44 J5.4
GPIO13: C8.1 CS1.1 J5.3 | length 1830.3
  Top Layer w10: C8.1@5355.1,1635.7 5355.1,1686.48 5352.6,1688.98 CS1.1 5240.16,1698.82 5177.17,1761.81 5177.17,1988.19 5531.5,2342.52 6043.31,2342.52 6211.02,2510.24 J5.3
IN+: CS1.4 CS2.3 J7.2 R5.2 R6.2 | length 1612.2
  Top Layer w25: CS1.4 5696.18,1801.18 5710,1815 5710,1918.66 R5.2 5723.66,1905 J7.2 6511.34,1905 R6.2 6525,1790 6545.59,1769.41 CS2.3
IN-: CS1.3 CS2.4 J7.1 R5.1 R6.1 | length 1627.6
  Top Layer w25: CS1.3 5691.18,1698.82 5705,1685 R5.1 5720.66,1572 6017,1572 J7.1 6084.74,1570.26 6506.08,1570.26 R6.1 6525,1655.95 6539.64,1670.59 CS2.4
NetC1_2: C1.2 R1.2 R2.2 | length 93.9
  Top Layer w6: C1.2 5426.83,3716.1 5434.33,3708.6 ; R2.2 5434.33,3708.6 ; R1.2 5434.33,3708.6
NetC9_2: C9.2 CS2.5 R7.1 R9.2 | length 145.3
  Top Layer w25: R9.2 6805.59,1610 ; C9.2 6805,1610.59 ; CS2.5 6805,1610.59 ; R7.1 6805.59,1610 ; 6805,1610.59 6805.59,1610
NetC10_2: C10.2 CS1.5 R8.1 R10.2 | length 155.7
  Top Layer w15: R8.1@5385.59,1861.06 5390,1856.65 CS1.5 ; R8.1 R10.2 5420.1,1869.31 5420.1,1889.15 5400,1909.25 C10.2
NetD2_2: D2.2 R11.1 | length 39.4
  Top Layer w30: D2.2 R11.1
NetDS1_4: DS1.4 DS2.2 | length 157.1
  Top Layer w10: DS2.2 5357.55,2795.28 5393.7,2795.28 5403.54,2785.43 5403.54,2742.08 5409.4,2736.22 5448.09,2736.22 DS1.4
RX: J5.2
TX: J5.1
VIN: P4.1
pads on no net: DS2.4 U1.5 U1.8

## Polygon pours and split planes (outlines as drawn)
3V3 on Top Layer "NONET_L-01_P-001" (solid, pour order 5): 5246.06,3277.56 5472.44,3277.56 5472.44,3248.03 5649.61,3248.03 5649.61,3159.45 5482.28,3159.45 5482.28,3001.97 5246.06,3001.97
NetC10_2 on Top Layer "NONET_L-01_P-001" (solid, pour order 2): 5374,1920 5374,1800 5410,1800 5410,1840 5440,1840 5450,1850 5450,1920
3V3 on Top Layer "NONET_L-01_P-001" (solid, pour order 4): 5310,1875 5310,1770 5370,1770 5370,1875
3V3 on Top Layer "NONET_L-01_P-001" (solid, pour order 3): 6830,1700 6830,1640 6860,1640 6860,1590 6910,1590 6910,1700
NetC1_2 on Top Layer "NONET_L-01_P-001" (solid, pour order 0): 5449.33,3666.1 5449.33,3751.1 5384.33,3751.1 5384.33,3666.1
GND on Top Layer "NONET_L-01_P-001" (solid, pour order 1): 5369.33,3666.1 5369.33,3756.1 5279.33,3756.1 5279.33,3666.1
GND on Layer 1 (split plane): 6987.78,1437.42 4272.07,1437.42 4272.07,3916.91 6987.78,3916.91
GND on Layer 2 (split plane): 6987.78,1437.42 4272.07,1437.42 4272.07,3916.91 6987.78,3916.91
